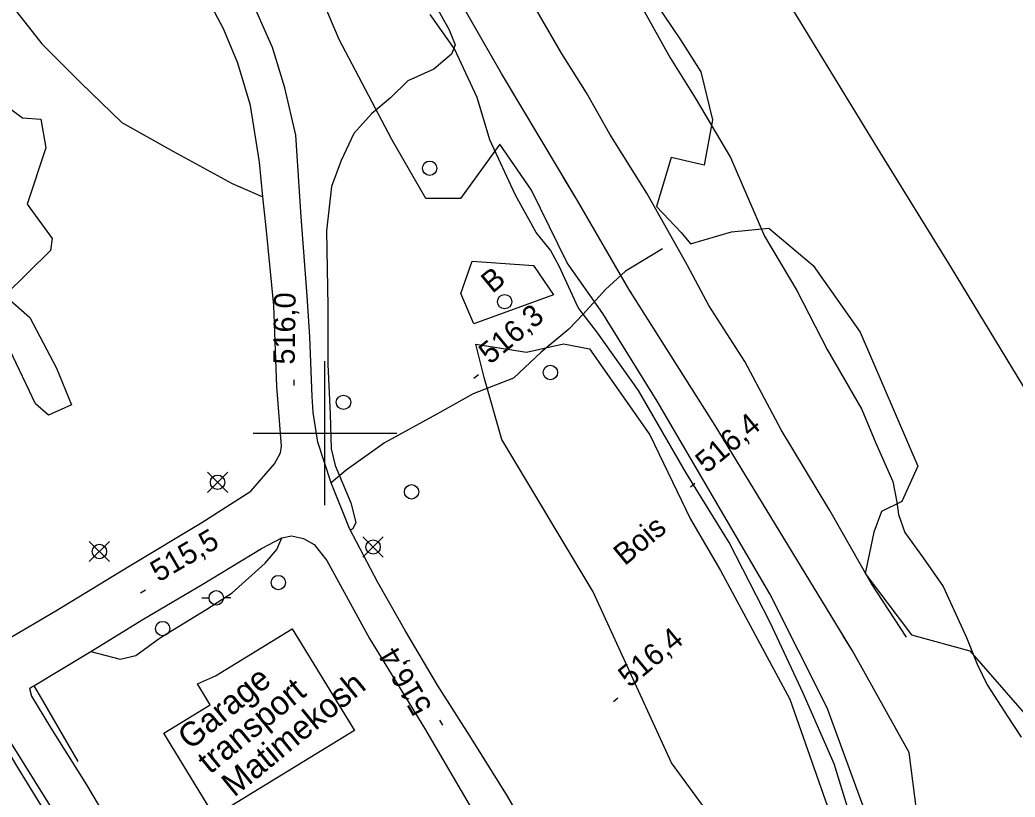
# Model space of a CAD drawing. Extents: x 347059 to 352153, y 6073752 to 6078601.
# Drawn here: x 349136.4 to 349344, y 6075224.1 to 6075386.2 of the extents above; entities that cross this region are included whole.
import ezdxf

# ---------------------------------------------------------------- set-up
doc = ezdxf.new("R2010")
doc.units = 0
for name, color, linetype in [('Level 19', 7, 'Continuous'), ('Level 2', 7, 'Continuous'), ('Level 21', 7, 'Continuous'), ('Level 22', 7, 'Continuous'), ('Level 25', 7, 'Continuous'), ('Level 3', 7, 'Continuous'), ('Level 31', 7, 'Continuous'), ('Level 36', 7, 'Continuous'), ('Level 37', 7, 'Continuous'), ('Level 4', 7, 'Continuous'), ('Level 44', 7, 'Continuous'), ('Level 61', 7, 'Continuous')]:
    doc.layers.add(name, color=color, linetype=linetype)

msp = doc.modelspace()

# ---------------------------------------------------------------- linework, layer by layer
at = {"layer": 'Level 19'}
msp.add_lwpolyline([(349151.15, 6075254.48), (349157.27, 6075252.83), (349160.56, 6075253.61), (349165.71, 6075257.35), (349175.38, 6075263.29), (349180.66, 6075266.68), (349187.51, 6075272.92), (349189.94, 6075275.74), (349190.99, 6075278.17)], dxfattribs=at)
at = {"layer": 'Level 2'}
for points in [[(349266.43, 6075439.8), (349266.64, 6075438.75), (349266.75, 6075418.1), (349265.56, 6075407.37), (349264.14, 6075394.95), (349266.33, 6075388.53), (349272.06, 6075378.3), (349277.23, 6075369.92), (349284.64, 6075357.48), (349291.74, 6075341.1), (349298.47, 6075329.75), (349304.8, 6075317.45), (349312, 6075304.91), (349314.92, 6075297.93)], [(349217.63, 6075398.98), (349225.91, 6075384.12), (349227.19, 6075380.98), (349226.44, 6075379.04), (349222.75, 6075375.95)], [(349222.75, 6075375.95), (349217.28, 6075373.47), (349213.69, 6075369.94), (349209.69, 6075366.59), (349206.05, 6075362.49), (349203.41, 6075356.86), (349201.35, 6075351.46), (349200.36, 6075342.22), (349200.61, 6075326.4), (349200.64, 6075314.34), (349201.11, 6075303.96), (349201.3, 6075296.76), (349202.12, 6075293.24), (349205.38, 6075285.47), (349206.42, 6075281.35), (349205.8, 6075280.06), (349205.29, 6075279.75)], [(349314.92, 6075297.93), (349318.5, 6075289.95), (349319.31, 6075285.6), (349319.65, 6075283.03), (349321.01, 6075279.29), (349324.82, 6075274), (349328.96, 6075268.03), (349333.88, 6075257.41), (349336.06, 6075251.8), (349338.19, 6075247.5), (349342.5, 6075240.86), (349345.28, 6075236.59)]]:
    msp.add_lwpolyline(points, dxfattribs=at)
at = {"layer": 'Level 21'}
for points in [[(349133.89, 6075257.11), (349143.87, 6075262.96), (349159.13, 6075272.26), (349174.32, 6075281.37), (349184.57, 6075287.89), (349189.46, 6075293.59), (349190.71, 6075295.9), (349190.96, 6075297.31), (349190, 6075309.76), (349189.35, 6075326.6), (349187.72, 6075342.92), (349187.06, 6075349.32), (349186.33, 6075356.51), (349184.45, 6075368.34), (349181.8, 6075377.2), (349178.82, 6075384.37), (349174.57, 6075392.44), (349167.97, 6075403.14), (349162.3, 6075412.36), (349154.7, 6075425.25), (349148.41, 6075435.4), (349140.97, 6075447.82), (349132.28, 6075461.83)], [(349246.53, 6075209.72), (349238.06, 6075224.28), (349230.6, 6075236.33), (349223.46, 6075247.44), (349216.76, 6075258.85), (349210.97, 6075268.97), (349205.1, 6075280.11), (349201.32, 6075289.63), (349198.55, 6075298.11), (349197.52, 6075304.3), (349197.35, 6075307.68), (349196.85, 6075320.12), (349196.3, 6075328.63), (349195.05, 6075345.12), (349193.94, 6075362.17), (349191.63, 6075372.07), (349189.09, 6075380.43), (349184.1, 6075391.65)], [(349138.84, 6075247.08), (349139.24, 6075247.32), (349150.11, 6075253.84), (349151.15, 6075254.48), (349161.88, 6075261.1), (349174.39, 6075268.45), (349186.76, 6075275.98), (349190.99, 6075278.17), (349193, 6075278.57), (349195.55, 6075278.04), (349197.75, 6075276.75), (349200.38, 6075273.46), (349209.3, 6075257.17), (349220.8, 6075238.49), (349230.57, 6075221.73)], [(349138.36, 6075246.77), (349138.84, 6075247.08)], [(349138.36, 6075246.77), (349138.8, 6075245.14), (349142.78, 6075238.6), (349150.24, 6075226.65), (349156.68, 6075215.85), (349161.32, 6075208.05), (349170.25, 6075193.15), (349175.45, 6075185.04), (349175.98, 6075184.22), (349181.91, 6075172.94), (349188.2, 6075161.42), (349194.46, 6075152.12), (349197.23, 6075145.67), (349200.31, 6075137.58), (349204.08, 6075129.93), (349205.3, 6075126.8), (349208.62, 6075123.88), (349210.81, 6075122.07), (349215.12, 6075119.23), (349217.88, 6075118.43), (349222, 6075117.64), (349229.97, 6075117.37), (349238.17, 6075116.83)], [(349128.46, 6075240.46), (349130.58, 6075240.18), (349132.01, 6075239.09), (349134.17, 6075235.85), (349142.14, 6075223.11), (349146.99, 6075215.24), (349155.29, 6075201.73), (349160.35, 6075193.52), (349166.68, 6075182.95), (349176.32, 6075169.21), (349183.43, 6075155.87), (349189.98, 6075143.59), (349194.29, 6075133.64), (349197.45, 6075127.45), (349200.47, 6075123.44), (349203.71, 6075121.18), (349207.46, 6075118.1), (349211.69, 6075114.81), (349217.07, 6075112.49), (349222.55, 6075112.24), (349226.37, 6075112.72), (349228.81, 6075113.41), (349233.08, 6075113.89), (349239.16, 6075113.46)]]:
    msp.add_lwpolyline(points, dxfattribs=at)
at = {"layer": 'Level 22'}
for points in [[(349030, 6075554.69), (349034.76, 6075546.97), (349042.02, 6075535.39), (349052.74, 6075517.49), (349057.88, 6075509.71), (349064.27, 6075498.45), (349071.64, 6075488), (349079.84, 6075476.74), (349090.07, 6075461.43), (349099.58, 6075445.52), (349107.36, 6075432.41), (349116.81, 6075416.76), (349125.77, 6075402.05), (349132, 6075392.61), (349140.93, 6075381.19), (349149.09, 6075373.05), (349157.66, 6075364.79), (349168.41, 6075358.78), (349180.66, 6075352.07), (349187.06, 6075349.32)], [(349310.39, 6075217.5), (349306.25, 6075231.01), (349299.79, 6075245.78), (349292.87, 6075260.49), (349284.31, 6075277.19), (349275.46, 6075291.6), (349265.42, 6075308.92), (349256.73, 6075321.11), (349253.88, 6075324.83), (349252.81, 6075326.23), (349248.86, 6075334.84), (349247.06, 6075338.17), (349244.06, 6075341.85), (349239.74, 6075349.64), (349234.4, 6075361.17), (349231.75, 6075370.04), (349227.01, 6075380.15), (349221.97, 6075387.3)], [(349270.43, 6075338.43), (349268.17, 6075337.09), (349262.74, 6075333.77), (349258.54, 6075329.99), (349253.88, 6075324.83), (349250.9, 6075321.7), (349245.12, 6075316.9), (349239.37, 6075311.51), (349230.93, 6075308.19), (349223.37, 6075303.96), (349212.43, 6075298), (349204.44, 6075292.3), (349201.32, 6075289.63)], [(349139.24, 6075247.32), (349140.8, 6075244.74), (349148.44, 6075231.49)], [(349167.32, 6075179.26), (349159.79, 6075191.27), (349153.08, 6075202.67), (349146.26, 6075213.46), (349135.75, 6075230.64), (349130.85, 6075238.85), (349130.27, 6075239.28), (349130.58, 6075240.18)]]:
    msp.add_lwpolyline(points, dxfattribs=at)
at = {"layer": 'Level 25'}
for points in [[(349125.41, 6075671.72), (349148.36, 6075633.86), (349165.68, 6075605.11), (349184.47, 6075574.59), (349202.41, 6075544.55), (349218.73, 6075518.25), (349237.22, 6075487.91), (349252.85, 6075462.09), (349274.18, 6075427.07), (349296.14, 6075390.76), (349315.26, 6075359.35)], [(349315.26, 6075359.35), (349330.66, 6075334.49), (349350.11, 6075302.45), (349365.7, 6075276.73), (349378.86, 6075254.66), (349394.02, 6075230.3), (349408.72, 6075206.12), (349426.04, 6075177.6), (349441.28, 6075152.62), (349453.47, 6075132.64), (349463.96, 6075115.56), (349465.34, 6075113.32), (349477.05, 6075094.13), (349472.68, 6075076.62), (349469.3, 6075062.36)]]:
    msp.add_lwpolyline(points, dxfattribs=at)
at = {"layer": 'Level 3'}
for p, q in [((349193.59, 6075309.96), (349193.61, 6075311.16)), ((349231.09, 6075311.49), (349232.01, 6075312.26)), ((349276.29, 6075288.79), (349277.21, 6075289.56)), ((349161.54, 6075266.68), (349162.57, 6075267.29)), ((349260.19, 6075244.06), (349261.11, 6075244.83)), ((349224.6, 6075239.11), (349223.99, 6075240.14))]:
    msp.add_line(p, q, dxfattribs=at)
at = {"layer": 'Level 31'}
msp.add_lwpolyline([(349177.15, 6075249.42), (349193.16, 6075259.22), (349206.15, 6075237.98), (349176.97, 6075220.14), (349166.39, 6075237.44), (349176.06, 6075243.36), (349173.39, 6075247.72), (349177.15, 6075249.42)], dxfattribs=at)
at = {"layer": 'Level 36'}
for p, q in [((349179.71, 6075287.64), (349175.48, 6075291.87)), ((349175.48, 6075287.64), (349179.71, 6075291.87)), ((349212.17, 6075274.14), (349207.94, 6075278.37)), ((349207.94, 6075274.14), (349212.17, 6075278.37)), ((349155.06, 6075273.2), (349150.83, 6075277.43)), ((349150.83, 6075273.2), (349155.06, 6075277.43)), ((349174.34, 6075265.66), (349175.84, 6075265.66)), ((349180.34, 6075265.66), (349178.84, 6075265.66))]:
    msp.add_line(p, q, dxfattribs=at)
for centre in [(349221.85, 6075355.27), (349237.5, 6075327.43), (349247.04, 6075312.66), (349203.88, 6075306.44), (349177.6, 6075289.76), (349218.07, 6075287.77), (349210.06, 6075276.26), (349152.95, 6075275.32), (349190.28, 6075268.84), (349177.33, 6075265.66), (349166.15, 6075259.25)]:
    msp.add_circle(centre, 1.5, dxfattribs=at)
at = {"layer": 'Level 37'}
for points in [[(349317.21, 6075032.18), (349341.51, 6075067.18), (349339.33, 6075091.36), (349335.89, 6075114.68), (349332.46, 6075145.46), (349329.55, 6075172.56), (349325.12, 6075208.38), (349321.87, 6075233.38), (349310.08, 6075254.61), (349281.44, 6075301.6), (349263.42, 6075330.01), (349252.75, 6075348.4), (349236.82, 6075375.05), (349227.95, 6075390.59), (349188.61, 6075453.08), (349160.73, 6075498.89), (349134.29, 6075542.79)], [(349239.53, 6075370.5), (349236.82, 6075375.05), (349236.47, 6075375.66)], [(349252.87, 6075348.19), (349252.75, 6075348.4), (349249.79, 6075353.34)], [(349263.95, 6075329.18), (349263.42, 6075330.01), (349260.9, 6075334.35)], [(349311.2, 6075252.59), (349310.08, 6075254.61), (349308.16, 6075257.76)], [(349321.88, 6075233.35), (349321.87, 6075233.38), (349318.97, 6075238.6)]]:
    msp.add_lwpolyline(points, dxfattribs=at)
at = {"layer": 'Level 4'}
msp.add_lwpolyline([(349321.31, 6075257.45), (349314, 6075268.7), (349305.35, 6075283.87), (349295.17, 6075300.71), (349287.62, 6075314.94), (349280.13, 6075326.66), (349275.64, 6075334.95), (349267.15, 6075350.04), (349259.47, 6075362.35), (349254.61, 6075371), (349249.38, 6075379.27), (349242.45, 6075391.22)], dxfattribs=at)
at = {"layer": 'Level 44'}
for points in [[(349126.08, 6075579.02), (349139.87, 6075558.81), (349151.15, 6075539.65), (349163.41, 6075518.77), (349175.57, 6075503.05), (349187.73, 6075486.43), (349195.02, 6075468.64), (349200.99, 6075456.04), (349213.04, 6075436.5), (349225.5, 6075417), (349229.9, 6075414.95), (349228.24, 6075428.11), (349213.71, 6075452.63), (349208.11, 6075465.67), (349208.89, 6075467.07), (349223.53, 6075453.43), (349234.56, 6075441.6), (349243.5, 6075429.39), (349256.48, 6075405.85), (349262.88, 6075398.87), (349274.19, 6075382.03), (349278.4, 6075375.34), (349280.84, 6075365.38), (349279.15, 6075355.89)], [(349236.47, 6075360.27), (349228.3, 6075348.95), (349221.06, 6075348.96), (349213.94, 6075361.28), (349202.98, 6075382.15), (349197.29, 6075395.63), (349177.75, 6075432.56), (349165.84, 6075450.64), (349152.65, 6075473.91), (349144.73, 6075483.99), (349128.57, 6075511.56)], [(349131.2, 6075369.95), (349136.92, 6075365.81), (349140.75, 6075365.47)], [(349140.75, 6075365.47), (349141.77, 6075359.55), (349137.88, 6075347.76), (349143.08, 6075340.63), (349142.77, 6075338.12), (349133.25, 6075328.74), (349138.44, 6075324.15), (349143.98, 6075313.54), (349147.15, 6075305.94), (349142.34, 6075303.76), (349139.59, 6075306.15), (349134.27, 6075317.4)], [(349333.47, 6075063.82), (349341.17, 6075068.8), (349340.5, 6075078.87), (349329.55, 6075078.27), (349328.06, 6075094.49), (349319.96, 6075111.06), (349322.96, 6075125.5), (349321.61, 6075154.18), (349320.62, 6075177.75), (349317.4, 6075198.08), (349315.16, 6075214.39), (349304.81, 6075242.69), (349292.86, 6075266.48), (349269.34, 6075306.68), (349257.98, 6075324.97), (349250.53, 6075335.5), (349243.1, 6075350.71), (349236.47, 6075360.27)], [(349279.15, 6075355.89), (349272.26, 6075357.52), (349269.21, 6075347.31), (349274.36, 6075341.83), (349276.28, 6075339.52), (349284.86, 6075341.99), (349292.62, 6075342.73), (349301.9, 6075334.99), (349311.67, 6075321.07), (349323.68, 6075293.12), (349320.38, 6075285.74), (349316.1, 6075283.68), (349314.56, 6075279.33), (349312.73, 6075270.75), (349322.35, 6075257.95), (349334.54, 6075254.62), (349346.84, 6075240.52)], [(349247.7, 6075328.89), (349231.07, 6075322.8), (349228.35, 6075329.13), (349230.7, 6075335.89), (349243.55, 6075335.01), (349247.7, 6075328.89)], [(349288.29, 6075209.41), (349272.31, 6075231.25), (349255.95, 6075266.89), (349236.93, 6075298.68), (349233.24, 6075311.58), (349231.49, 6075318.55), (349242.06, 6075316.91), (349249.81, 6075318.65), (349255.23, 6075317.58), (349267.78, 6075299.68), (349276.26, 6075282.07), (349282.56, 6075271.36), (349296.97, 6075244.53), (349305.75, 6075219.59)]]:
    msp.add_lwpolyline(points, dxfattribs=at)
at = {"layer": 'Level 61'}
for p, q in [((349200, 6075285), (349200, 6075315)), ((349185, 6075300), (349215, 6075300))]:
    msp.add_line(p, q, dxfattribs=at)

# ---------------------------------------------------------------- texts
at = {"layer": 'Level 3'}
for s, rotation, p in [('516,0', 89.216, (349193.7, 6075314.28)), ('516,3', 39.62, (349234.45, 6075314.2)), ('516,4', 39.62, (349279.65, 6075291.5)), ('515,5', 30.3554, (349165.29, 6075268.82)), ('516,4', 39.62, (349263.55, 6075246.78)), ('516,4', 120.2637, (349222.46, 6075242.86))]:
    msp.add_text(s, height=4.5, rotation=rotation, dxfattribs=at).set_placement(p)
at = {"layer": 'Level 31'}
for s, p in [('Garage', (349171.91, 6075233.76)), ('transport', (349176.02, 6075228.73)), ('Matimekosh', (349181.06, 6075223.94))]:
    msp.add_text(s, height=5, rotation=39.3712, dxfattribs=at).set_placement(p)
at = {"layer": 'Level 44'}
for s, p in [('B', (349234.94, 6075329.01)), ('Bois', (349262.56, 6075272.22))]:
    msp.add_text(s, height=4.5, rotation=39.568, dxfattribs=at).set_placement(p)

doc.saveas('drawing.dxf')
